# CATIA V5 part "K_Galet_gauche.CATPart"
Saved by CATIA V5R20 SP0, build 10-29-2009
Part number: Galet_gauche
Bounding box of the stored display mesh (mm): x 0 to 17.955, y -11.571 to 11.571, z -11.571 to 11.571
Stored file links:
  G:\Khaled_CFAO_2011\SIL\SIL_GR2\zthiebault\Khaled\CAD_ThinkMOTION\K_Galet_gauche.CATPart
  G:\Khaled_CFAO_2011\SIL\SIL_GR2\zthiebault\CATIA_zthiebault\Galet_droit.CATPart
  F:\Projet Thinkmotion\Catia\FINAL\HabillageFinal.CATProduct
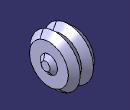
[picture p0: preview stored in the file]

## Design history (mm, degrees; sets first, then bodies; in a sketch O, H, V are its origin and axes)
Parameters
  LENGTH = 10.41 mm
  LENGTH = 9 mm
Set1
  Line1 "Droite_base_galetdroit": linked copy from another document
  Plane1 "Plan_base_galet_cerclecontact": linked copy from another document
Body1 (main body)
  Sketch1 on zx-plane, origin (0, 0, 0), H (-1, 0, 0), V (0, 0, 1)
    line L1 (0, 0) -> (-17.9551, 0)
    line L2 (-17.9551, 0) -> (-17.9551, -2)
    line L3 (-17.9551, -2) -> (-16.41, -3.9654)
    point P4 (-16.41, -3.9654)
    line L4 (-16.41, -3.9654) -> (-16.41, -8.9654)
    line L5 (-16.41, -8.9654) -> (-13.4742, -11.5712)
    line L6 (-13.4742, -11.5712) -> (-10.41, -9)
    point P7 (-10.41, -9)
    line L7 (-10.41, -9) -> (-7.3458, -11.5712)
    line L8 (-7.3458, -11.5712) -> (-4.41, -9)
    line L9 (-4.41, -9) -> (-4.41, -3)
    line L10 (-4.41, -3) -> (-1.3229, -3)
    line L11 (-1.3229, -3) -> (0, -1.5)
    line L12 (0, -1.5) -> (0, 0)
    construction line L13 (-13.4742, -11.5712) -> (-7.3458, -11.5712)
    axis line L14 (-4.41, -9) -> (-10.41, -9)
    reference projected line E1 (0, 0) -> (-10.41, 0) from Line1
    reference intersected line E2 through (-10.41, 0) direction (0, -1) from Plane1
    length L2 = 2
    length L4 = 5
    angle L6 L7 = 100
    length L6 = 4
    length L7 = 4 {= Sketch1.length(L6)}
    length L9 = 6
    length L11 = 2
    distance L1 P7 = 9 {= LENGTH}
    distance L4 P7 = 6
    length L12 = 1.5
    distance L12 P7 = 10.41 {= LENGTH}
    distance L9 P7 = 6 {= Sketch1.distance(L4 P7)}
    length L3 = 2.5
    horizontal: L1 H, L10 H, L13 H, L14 H
    vertical: L2 V, L4 V, L9 V, L12 V
    coincidence: L7 P4, L1 E1, E2 P7
  Shaft1: profile Sketch1, axis Sketch1.L1, angle 360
